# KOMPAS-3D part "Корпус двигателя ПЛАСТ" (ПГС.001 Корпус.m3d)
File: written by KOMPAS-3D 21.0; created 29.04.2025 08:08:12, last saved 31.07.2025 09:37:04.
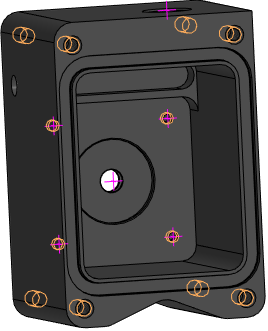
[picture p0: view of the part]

Document properties: Автор: User; Полное имя файла: C:\Users\User\Desktop\ПЕРСПЕКТИВА кд\Модель\ПГС.001 Корпус.m3d

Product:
- Part/product: Корпус двигателя ПЛАСТ
    Масса: 0.864545
    Форматы листов документа: 2xA3
  - Body: Тело 1
      Масса: 0.862842

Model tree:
1. Эскиз:1
2. Элемент выдавливания:1
     Расстояние 1 = 40; Расстояние 2 = 40
3. Эскиз:2  (with: Элемент выдавливания:1)
4. Элемент выдавливания:2
     Расстояние 2 = 46.3
5. Элемент выдавливания:3
     Расстояние 2 = 52.3
6. Эскиз:3  (with: Элемент выдавливания:1, Элемент выдавливания:2)
7. Элемент выдавливания:4
     Толщина стенки 1 = 3.5; Расстояние 2 = 1.85
8. Эскиз:4  (with: Элемент выдавливания:1)
9. Эскиз:7  (with: Элемент выдавливания:1, Элемент выдавливания:3)
10. Эскиз:8  (with: Элемент выдавливания:2)
11. Элемент выдавливания:7
     Расстояние 1 = 8
12. Скругление:1  (with: Элемент выдавливания:7)
     Радиус = 4
13. Эскиз:9  (with: Элемент выдавливания:2, Элемент выдавливания:3)
14. Отверстие:1  (with: Элемент выдавливания:2, Элемент выдавливания:7)  (labels: M3)
     Глубина выреза = 4; Диаметр отверстия = 2.45873; Угол конуса дна = 118; Расстояние 1 = -6; Расстояние 2 = 6.16587
15. M3  (with: Элемент выдавливания:2)  (labels: M3; cil0_24705-2004 coarse)
     Длина резьбы = 2; Шаг резьбы = 0.5; Номинальный диаметр резьбы = 3
16. Массив по точкам:1
17. Экземпляр ( 3 )  (with: Отверстие:1)  (labels: M3)
18. Экземпляр ( 1 )  (with: Отверстие:1)  (labels: M3)
19. Экземпляр ( 2 )  (with: Отверстие:1)  (labels: M3)
20. Отверстие:2  (with: Элемент выдавливания:1)  (labels: M4)
     Глубина выреза = 10; Диаметр отверстия = 3.24223; Угол конуса дна = 118; Расстояние 1 = 74; Расстояние 2 = 49; Диаметр зенковки = 5; Глубина зенковки = 0.878886; Угол зенковки = 90
21. M4  (labels: cil0_24705-2004 coarse)
     Длина резьбы = 8; Шаг резьбы = 0.7; Номинальный диаметр резьбы = 4
22. Массив по точкам:2  (with: Экземпляр ( 2 ), Отверстие:2, Эскиз:4)  (labels: M4)
23. Экземпляр ( 3 )  (with: Отверстие:2, Эскиз:4)  (labels: M4)
24. Экземпляр ( 1 )  (with: Отверстие:2, Эскиз:4)  (labels: M4)
25. Зеркальный массив:1  (with: Экземпляр ( 1 ), Экземпляр ( 2 ), Отверстие:2)
26. Массив по точкам:2  (with: Экземпляр ( 2 ), Отверстие:2)
27. Экземпляр ( 3 )  (with: Отверстие:2)
28. Экземпляр ( 1 )  (with: Отверстие:2)
29. Эскиз:10  (with: Элемент выдавливания:7)
30. Элемент выдавливания:8  (with: Элемент выдавливания:2)
     Расстояние 2 = 6
31. Скругление:2  (with: Элемент выдавливания:1)
     Радиус = 5
32. Эскиз:13  (with: Элемент выдавливания:1)
33. Отверстие:3  (with: Элемент выдавливания:1, Скругление:2)
     Глубина выреза = 18; Диаметр отверстия = 8; Угол конуса дна = 118; Расстояние 1 = 32; Расстояние 2 = 22.15; Диаметр цековки = 12; Глубина цековки = 2.8
34. Фаска:1  (with: Отверстие:3)
     Угол = 45; Длина 1 = 0.5; Длина 2 = 0.5
35. Фаска:2  (with: Отверстие:3)
     Угол = 45; Длина 1 = 0.3; Длина 2 = 0.3
36. Эскиз:14  (with: Элемент выдавливания:3)
37. Элемент вращения:1
     Угол 1 = 360
38. Фаска:3  (with: Элемент выдавливания:3, Элемент вращения:1)
     Угол = 45; Длина 1 = 0.3; Длина 2 = 0.3
39. Фаска:4  (with: Элемент вращения:1)
     Угол = 45; Длина 1 = 0.15; Длина 2 = 0.15
40. Эскиз:15
41. Элемент выдавливания:11
     Расстояние 1 = 63; Расстояние 2 = 33
42. Скругление:4  (with: Элемент выдавливания:1, Элемент выдавливания:11)
     Радиус = 5
43. Скругление:5  (with: Элемент выдавливания:4)
     Радиус = 0.2
44. Эскиз:16  (with: Элемент выдавливания:1, Элемент выдавливания:8)
45. Элемент выдавливания:12
     Расстояние 2 = 10

Referenced files in C:\Users\User\Desktop\П7\: П7.a3d
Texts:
  Точка начала. Х
  Точка начала. Y
  Точка начала. Z
  Линейный размер с обрывом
